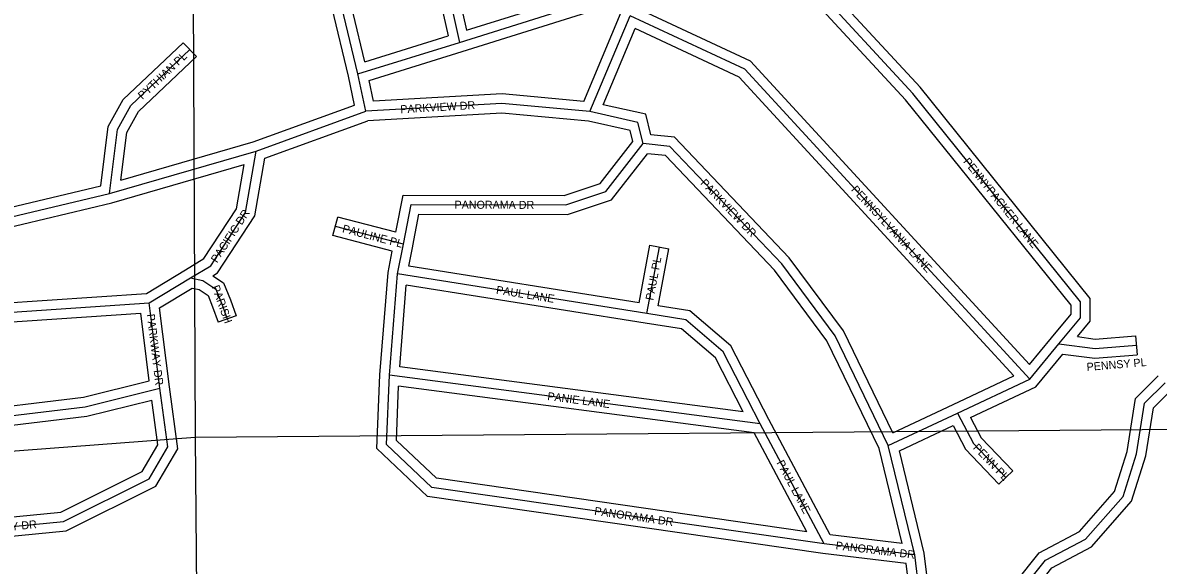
# Model space of a CAD drawing. Extents: x 457167 to 656239, y 1787309 to 1969297.
# Drawn here: x 584541 to 588088, y 1892821 to 1894517 of the extents above; entities that cross this region are included whole.
import ezdxf

# ---------------------------------------------------------------- set-up
doc = ezdxf.new("R2010")
doc.units = 0
for name, color, linetype in [('Level 1', 7, 'Continuous'), ('Level 31', 7, 'Continuous'), ('Level 32', 7, 'Continuous'), ('Level 34', 7, 'Continuous')]:
    doc.layers.add(name, color=color, linetype=linetype)

msp = doc.modelspace()

# ---------------------------------------------------------------- linework, layer by layer
at = {"layer": 'Level 1'}
for p, q in [((585054.368, 1898486.937), (585080.121, 1893221.401)), ((585080.121, 1893221.401), (589867.16, 1893260.646)), ((579855.256, 1892821.831), (585080.121, 1893221.401)), ((585080.121, 1893221.401), (585126.331, 1887669.13))]:
    msp.add_line(p, q, dxfattribs=at)
at = {"layer": 'Level 31'}
for p, q in [((585855.165, 1894681.764), (585904.979, 1894455.486)), ((585587.76, 1894356.816), (585538.233, 1894565.276)), ((586312.866, 1894239.075), (586438.397, 1894538.841)), ((585587.76, 1894356.816), (585904.979, 1894455.486)), ((585612.659, 1894240.04), (585587.76, 1894356.816)), ((585270.586, 1894115.601), (585612.659, 1894240.04)), ((584812.11, 1893983.026), (585270.586, 1894115.601)), ((585730.164, 1893824.539), (585517.534, 1893880.217)), ((585711.862, 1893731.482), (585730.164, 1893824.539)), ((586490.391, 1893607.461), (586529.893, 1893815.389)), ((584936.425, 1893640.965), (585065.044, 1893718.9)), ((585686.459, 1893414.801), (585711.862, 1893731.482)), ((586490.391, 1893607.461), (585711.862, 1893731.482)), ((583861.15, 1893567.777), (584936.425, 1893640.965)), ((584969.304, 1893374.354), (584936.425, 1893640.965)), ((587687.256, 1893403.045), (587778.086, 1893512.696)), ((586844.945, 1893262.792), (585686.459, 1893414.801)), ((587460.648, 1893296.554), (587687.256, 1893403.045)), ((587244.859, 1893195.5), (587460.648, 1893296.554)), ((587044.268, 1892887.507), (586844.945, 1893262.792)), ((587327.859, 1892853.524), (587244.859, 1893195.5)), ((587327.859, 1892853.524), (587044.268, 1892887.507)), ((587385.508, 1892386.503), (587327.859, 1892853.524))]:
    msp.add_line(p, q, dxfattribs=at)
for points in [[(585904.979, 1894455.486), (586280.104, 1894572.595), (586698.984, 1895814.001)], [(587778.086, 1893512.696), (587845.652, 1893594.753), (587845.743, 1893644.572), (587321.626, 1894295.731), (587005.548, 1894638.141), (586563.958, 1894855.336)], [(587687.256, 1893403.045), (586796.772, 1894371.621), (586438.397, 1894538.841)], [(584812.11, 1893983.026), (584837.297, 1894182.981), (584879.098, 1894258.173), (585062.91, 1894432.73)], [(586312.866, 1894239.075), (586037.854, 1894264.322), (585612.659, 1894240.04)], [(586479.621, 1894138.76), (586462.893, 1894205.337), (586312.866, 1894239.075)], [(585730.164, 1893824.539), (585753.929, 1893948.131), (586237.589, 1893947.214), (586362.638, 1893988.796), (586479.621, 1894138.76)], [(587244.859, 1893195.5), (587078.865, 1893537.631), (586912.339, 1893763.035), (586562.918, 1894130.24), (586479.621, 1894138.76)], [(585065.044, 1893718.9), (585128.397, 1893757.325), (585237.149, 1893924.026), (585270.586, 1894115.601)], [(583836.579, 1893851.101), (584395.034, 1893883.468), (584812.11, 1893983.026)], [(585065.044, 1893718.9), (585103.504, 1893710.826), (585144.155, 1893683.476), (585161.562, 1893639.806), (585179.275, 1893590.68)], [(586844.945, 1893262.792), (586728.662, 1893488.104), (586612.146, 1893588.323), (586490.391, 1893607.461)], [(587778.086, 1893512.696), (587890.947, 1893497.942), (588020.072, 1893508.613)], [(587044.268, 1892887.507), (585819.353, 1893064.361), (585677.779, 1893198.087), (585686.459, 1893414.801)], [(587702.238, 1892386.28), (587635.887, 1892619.496), (587669.523, 1892752.89), (587736.139, 1892836.403), (587861.234, 1892902.718), (587978.184, 1893035.959), (588020.085, 1893169.337), (588045.497, 1893327.474), (588109.531, 1893391.356)], [(583910.394, 1893217.496), (584735.784, 1893316.258), (584969.304, 1893374.354)], [(583910.394, 1893217.496), (583976.881, 1893067.182), (584085.109, 1892958.97), (584251.658, 1892916.827), (584668.633, 1892957.838), (584935.689, 1893090.779), (584994.074, 1893190.668), (584969.304, 1893374.354)], [(587460.648, 1893296.554), (587510.716, 1893201.551), (587612.277, 1893094.816)]]:
    msp.add_lwpolyline(points, dxfattribs=at)
at = {"layer": 'Level 32'}
for p, q in [((585833.256, 1894641.747), (585869.757, 1894475.946)), ((585889.877, 1894663.632), (585927.249, 1894493.866)), ((585558.493, 1894350.219), (585507.988, 1894562.79)), ((585609.524, 1894395.002), (585573.577, 1894546.302)), ((586293.695, 1894270.961), (586410.616, 1894550.167)), ((586354.36, 1894260.493), (586454.009, 1894498.451)), ((585042.251, 1894454.485), (585083.569, 1894410.976)), ((585609.524, 1894395.002), (585869.756, 1894475.946)), ((585622.811, 1894336.299), (585913.89, 1894426.838)), ((585577.877, 1894259.31), (585558.494, 1894350.219)), ((585636.636, 1894271.457), (585622.81, 1894336.298)), ((585261.281, 1894144.139), (585577.877, 1894259.31)), ((585297.155, 1894093.341), (585618.773, 1894210.338)), ((584847.574, 1894024.51), (585261.281, 1894144.139)), ((584819.765, 1893954.009), (585232.774, 1894073.436)), ((585509.935, 1893851.195), (585525.134, 1893909.239)), ((585706.756, 1893861.68), (585525.134, 1893909.239)), ((585695.286, 1893802.659), (585509.935, 1893851.195)), ((585747.302, 1893756.215), (585759.6, 1893818.749)), ((586466.354, 1893641.669), (586500.42, 1893820.988)), ((586500.42, 1893820.988), (586559.367, 1893809.789)), ((585682.096, 1893735.589), (585695.286, 1893802.659)), ((586525.646, 1893632.288), (586559.367, 1893809.789)), ((584927.114, 1893670.4), (585049.497, 1893744.557)), ((586466.354, 1893641.669), (585747.302, 1893756.215)), ((585656.507, 1893416.6), (585682.096, 1893735.59)), ((584968.577, 1893625.367), (585070.466, 1893687.107)), ((585718.644, 1893440.833), (585739.174, 1893696.751)), ((586485.672, 1893577.834), (585739.174, 1893696.752)), ((583883.37, 1893599.358), (584927.114, 1893670.4)), ((583895.377, 1893540.036), (584910.128, 1893609.104)), ((584936.278, 1893397.051), (584910.127, 1893609.104)), ((584999.035, 1893378.362), (584968.578, 1893625.367)), ((585207.497, 1893600.856), (585151.053, 1893580.504)), ((587686.079, 1893448.651), (587754.983, 1893531.834)), ((588017.6, 1893538.512), (588022.543, 1893478.714)), ((587706.084, 1893378.742), (587790.624, 1893480.801)), ((586791.984, 1893299.999), (585718.644, 1893440.834)), ((587447.889, 1893323.706), (587637.519, 1893412.818)), ((586825.708, 1893235.057), (585715.122, 1893380.781)), ((587501.83, 1893282.758), (587706.084, 1893378.743)), ((587258.934, 1893235.217), (587447.924, 1893323.723)), ((587063.408, 1892915.429), (586871.441, 1893276.865)), ((587279.801, 1893178.734), (587447.453, 1893257.246)), ((586990.042, 1892925.646), (586825.708, 1893235.058)), ((587288.511, 1892888.454), (587216.465, 1893185.297)), ((587357.423, 1892858.917), (587279.801, 1893178.734)), ((587634.01, 1893115.497), (587590.544, 1893074.136)), ((587288.511, 1892888.454), (587063.409, 1892915.429)), ((587300.964, 1892826.531), (587040.339, 1892857.761)), ((587412.035, 1892416.484), (587357.423, 1892858.916)), ((587355.285, 1892386.465), (587300.964, 1892826.531))]:
    msp.add_line(p, q, dxfattribs=at)
for points in [[(585913.919, 1894426.848), (586303.642, 1894548.514), (586717.633, 1895775.432)], [(585927.249, 1894493.866), (586256.567, 1894596.675), (586660.935, 1895795.074)], [(587835.663, 1893535.424), (587875.632, 1893583.967), (587875.762, 1893655.121), (587344.359, 1894315.333), (587023.802, 1894662.596), (586602.313, 1894869.903)], [(587754.926, 1893531.766), (587815.671, 1893605.539), (587815.723, 1893634.022), (587298.892, 1894276.128), (586987.294, 1894613.686), (586579.866, 1894814.077)], [(587686.079, 1893448.651), (586814.838, 1894396.296), (586476.714, 1894554.067)], [(587637.519, 1893412.819), (586778.706, 1894346.945), (586454.009, 1894498.451)], [(584784.942, 1894007.383), (584808.258, 1894192.486), (584855.108, 1894276.765), (585042.251, 1894454.485)], [(584847.574, 1894024.51), (584866.337, 1894173.474), (584903.088, 1894239.581), (585083.569, 1894410.976)], [(586293.695, 1894270.961), (586038.373, 1894294.401), (585636.636, 1894271.458)], [(586503.594, 1894166.464), (586487.489, 1894230.556), (586354.361, 1894260.492)], [(586308.184, 1894209.376), (586037.335, 1894234.243), (585618.774, 1894210.338)], [(586446.956, 1894145.659), (586438.296, 1894180.118), (586308.184, 1894209.377)], [(585706.756, 1893861.68), (585729.156, 1893978.18), (586232.76, 1893977.224), (586344.563, 1894014.402), (586446.956, 1894145.659)], [(587258.935, 1893235.217), (587104.644, 1893553.224), (586935.359, 1893782.363), (586577.004, 1894158.956), (586503.594, 1894166.465)], [(585759.624, 1893818.874), (585778.701, 1893918.084), (586242.419, 1893917.205), (586380.712, 1893963.191), (586493.073, 1894107.226)], [(587216.465, 1893185.296), (587053.086, 1893522.036), (586889.319, 1893743.707), (586548.831, 1894101.523), (586493.073, 1894107.226)], [(585049.485, 1893744.551), (585107.001, 1893779.436), (585208.656, 1893935.257), (585232.774, 1894073.436)], [(585134.655, 1893726.026), (585149.793, 1893735.214), (585265.644, 1893912.796), (585297.155, 1894093.341)], [(583835.741, 1893881.102), (584390.649, 1893913.265), (584784.941, 1894007.384)], [(583865.155, 1893822.705), (584399.419, 1893853.671), (584819.765, 1893954.009)], [(585134.655, 1893726.026), (585168.592, 1893703.193), (585189.614, 1893650.451), (585207.497, 1893600.856)], [(585070.467, 1893687.106), (585091.614, 1893682.669), (585119.718, 1893663.758), (585133.509, 1893629.16), (585151.053, 1893580.504)], [(586871.441, 1893276.865), (586752.646, 1893507.046), (586625.238, 1893616.635), (586525.646, 1893632.288)], [(586791.984, 1893299.999), (586704.678, 1893469.162), (586599.055, 1893560.011), (586485.733, 1893577.825)], [(587835.664, 1893535.424), (587891.664, 1893528.104), (588017.6, 1893538.512)], [(587790.624, 1893480.801), (587890.229, 1893467.78), (588022.543, 1893478.714)], [(583936.032, 1893250.777), (584730.359, 1893345.824), (584936.277, 1893397.051)], [(587040.339, 1892857.761), (585805.66, 1893036.026), (585647.257, 1893185.651), (585656.506, 1893416.6)], [(587662.504, 1892416.308), (587604.829, 1892619.027), (587642.021, 1892766.521), (587716.576, 1892859.988), (587842.318, 1892926.646), (587951.459, 1893050.991), (587990.811, 1893176.25), (588017.421, 1893341.841), (588088.344, 1893412.595)], [(583881.264, 1893209.189), (583951.71, 1893049.926), (584069.739, 1892931.912), (584249.379, 1892886.457), (584677.062, 1892928.521), (584957.071, 1893067.911), (585025.185, 1893184.444), (584999.035, 1893378.362)], [(586990.041, 1892925.647), (585833.045, 1893092.696), (585708.303, 1893210.525), (585715.122, 1893380.781)], [(587721.482, 1892428.277), (587666.945, 1892619.965), (587697.025, 1892739.257), (587755.702, 1892812.819), (587880.149, 1892878.791), (588004.908, 1893020.926), (588049.36, 1893162.425), (588073.574, 1893313.106), (588130.719, 1893370.117)], [(583954.244, 1893192.526), (584741.208, 1893286.692), (584944.049, 1893337.155)], [(583954.244, 1893192.526), (584002.052, 1893084.438), (584100.478, 1892986.027), (584253.937, 1892947.197), (584660.204, 1892987.155), (584914.305, 1893113.647), (584962.962, 1893196.892), (584944.049, 1893337.155)], [(587501.831, 1893282.758), (587535.317, 1893219.218), (587634.01, 1893115.497)], [(587447.453, 1893257.246), (587486.114, 1893183.884), (587590.544, 1893074.136)]]:
    msp.add_lwpolyline(points, dxfattribs=at)

# ---------------------------------------------------------------- texts
at = {"layer": 'Level 34'}
for s, height, rotation, p in [('PYTHIAN PL', 25, 43.519803, (584915.206, 1894275.226)), ('PARKVIEW DR', 25, 3.268306, (585721.259, 1894233.722)), ('PENNYPACKER LANE', 25, 308.830256, (587477.673, 1894081.925)), ('PARKVIEW DR', 25, 313.578203, (586656.274, 1894014)), ('PENNSYLVANIA LANE', 25, 312.594383, (587127.294, 1893993.645)), ('PANORAMA DR', 25, 359.891078, (585889.909, 1893935.374)), ('PACIFIC DR', 25, 56.879483, (585147.809, 1893764.206)), ('PAULINE PL', 25, 345.326017, (585537.503, 1893862.067)), ('PAUL PL', 25, 79.242158, (586510.694, 1893647.362)), ('PARISH', 25, 289.827906, (585130.644, 1893691.287)), ('PAUL LANE', 24.9992, 350.948564, (586018.449, 1893669.986)), ('PARKWAY DR', 25, 277.029542, (584928.259, 1893605.066)), ('PENNSY PL', 25, 4.724003, (587865.489, 1893428.269)), ('PANIE LANE', 25, 352.524589, (586178.822, 1893337.589)), ('PENN PL', 25, 313.577189, (587507.824, 1893186.456)), ('PAUL LANE', 25, 297.973242, (586895.229, 1893141.471)), ('PANORAMA DR', 25, 351.784117, (586325.283, 1892978.686)), ('PARKWAY DR', 25, 5.616797, (584362.162, 1892915.136)), ('PANORAMA DR', 25, 353.1665, (587079.501, 1892870.696))]:
    msp.add_text(s, height=height, rotation=rotation, dxfattribs=at).set_placement(p)

doc.saveas('drawing.dxf')
